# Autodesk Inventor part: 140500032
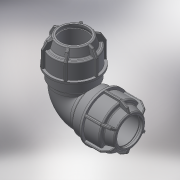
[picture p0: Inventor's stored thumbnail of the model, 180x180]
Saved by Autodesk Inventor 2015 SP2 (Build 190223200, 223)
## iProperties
Created: 2017-08
Part Number: 140500032
Material: Generic
Description: PLASSON L.14 90° ELBOW (SILVER) 32-32
Document SubType Name: Modeling
Designer: KIM
Density: 1 g/cm^3
Appearance: Default
Author: KIM
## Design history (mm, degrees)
derived "140500.ipt"
feature "Solid1::140500.ipt"
tag "TaggingFeature1"
body "Solid1"
other parameters: "d1" = 32, "d2" = 58, "d4" = 15 deg, "d5" = 38.28, "d6" = 12.6324, "d10" = 61, "d16" = 32.64, "d17" = 2.9, "d22" = 51.2, "d24" = 2.9, "d25" = 54.9, "d26" = 45.75, "d27" = 2.9, "d28" = 135 deg, "d29" = 1.74, "d31" = 1.6, "d46" = 150 deg, "d49" = 3.05, "d50" = 0, "d58" = 0.96, "d61" = 360 deg, "d63" = 28.8, "d80" = 46.08, "d81" = 2.56, "d84" = 2.9, "d112" = 75, "d113" = 0.75, "d115" = 90 deg, "d_" = 32, "E_" = 61, "A_" = 75, "l_" = 58
